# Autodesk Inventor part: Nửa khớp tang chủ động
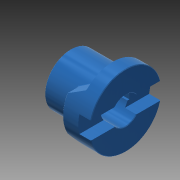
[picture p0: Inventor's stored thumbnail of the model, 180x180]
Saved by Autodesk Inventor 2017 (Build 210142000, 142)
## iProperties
Created: 2011-05
Part Number: Nửa khớp tang chủ động
Document SubType Name: Modeling
Designer: Administrator
Density: 7.85 g/cm^3
Material: Steel
Mass: 37857.7 g
Surface Area: 2677.23 cm^2
Volume: 4822.63 cm^3
Appearance: Cyan
Author: Administrator
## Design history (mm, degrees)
sketch "Sketch1"
  geometry: L1 (0, 0)-(192, 0); L2 (192, 47.5)-(192, 125); L3 (192, 125)-(147, 125); L4 (147, 125)-(147, 90); L5 (147, 90)-(0, 90); L6 (0, 90)-(0, 47.5); L7 (0, 47.5)-(192, 47.5)
  constraints: 14 end point, 2 horizontal, 2 parallel, 1 point on line, 1 vertical
  dimensions: "d0" = 180 diameter of L5 L1; "d1" = 250 diameter of L3 L1; "d2" = 192 distance between parallel lines of L2 L6; "d3" = 45 distance of L2.end L3.end; "d70" = 95 diameter of L7 L1
revolve "Revolution2" sketch "Sketch1" stored, may be unused: angle "d31" = 90 deg
sketch "Sketch6"
  geometry: L1 (-97, 60)-(-97, -60); L2 (0, 90)-(0, 47.5) reference; L3 (0, -90)-(-147, -90) reference; L4 (-147, 125)-(-147, 90) reference; L5 (-192, 125)-(-147, 125) reference; L6 (-147, -125)-(-192, -125) reference; L7 (-147, -90)-(-147, -125) reference; L8 (-147, 90)-(0, 90) reference; L9 (-192, 125)-(-192, -125) reference; L10 (-147, 125)-(-147, -125) reference; L11 (0, 0)-(-192, 0); L12 (-97, -60)-(-147, -85); L13 (-97, 60)-(-147, 85); L14 (0, 47.5)-(-192, 47.5) reference; L15 (-192, 47.5)-(-192, 125) reference; L16 (-192, -47.5)-(0, -47.5) reference; L17 (0, -47.5)-(0, -90) reference; L18 (-192, -125)-(-192, -47.5) reference
  constraints: 8 end point, 2 point on line, 1 midpoint, 1 vertical
  dimensions: "d34" = 120 distance of L1.start L1.end; "d35" = 120 diameter of L1.start L11; "d59" = 50 distance between parallel lines of L1 L10; "d60" = 170 distance of L13.end L12.end; "d61" = 170 diameter of L12.end L11
extrude "Extrusion3" join sketch "Sketch6" stored distance "d36" = 10; taper "d37" = 0 deg
mirror "Mirror1"
sketch "Sketch8"
  geometry: L1 (30, 121.347)-(30, -121.347); L2 (-30, 121.347)-(-30, -121.347); A1 r 125 centre (0, 0) between (-30, 121.347) and (30, 121.347) reference
  constraints: 4 end point, 4 point on circle, 1 parallel, 1 vertical
  dimensions: "d43" = 30 distance from line of A1.centre L2 (= 0.5 x d44); "d44" = 60 distance between parallel lines of L1 L2
extrude "Extrusion5" cut sketch "Sketch8" distance "d45" = 40; taper "d46" = 0 deg
sketch "Sketch9" dims "d47" = 95
  geometry: L1 (0, 85.755)-(0, 0); C1 r 90 at (0, 0) reference; 2 further points
  constraints: 2 coincident, 2 end point, 1 point on line, 1 vertical, 1 vertical alignment, 2 other
extrude "Extrusion6" cut sketch "Sketch9" stored distance "d51" = 50; taper "d52" = 0 deg
chamfer "Chamfer2" distance "d56" = 2; stored, may be unused: second distance "d57" = 2, angle "d58" = 45 deg
fillet "Fillet1" dims "d68" = 5
fillet "Fillet2" dims "d69" = 5
sketch "Sketch10"
  geometry: L1 (12.5, 32.9)-(-12.5, 32.9); L2 (-12.5, 32.9)-(-12.5, 52.9); L3 (-12.5, 52.9)-(12.5, 52.9); L4 (12.5, 52.9)-(12.5, 32.9); C1 r 47.5 at (0, 0) reference; 2 further points
  constraints: 8 end point, 2 parallel, 1 horizontal, 1 midpoint, 1 perpendicular, 1 vertical alignment
  dimensions: "d71" = 25 distance of L2.end L3.end; "d72" = 5.4 distance edge to line of C1 L3; "d73" = 20 distance of L1.end L2.end
extrude "Extrusion7" cut sketch "Sketch10" stored distance "d74" = 10; taper "d75" = 0 deg
body "Solid2"
node "Projected Loop1"
node "Project Cut Edges3"
other parameters: "d11" = 35.5, "d12" = 71
